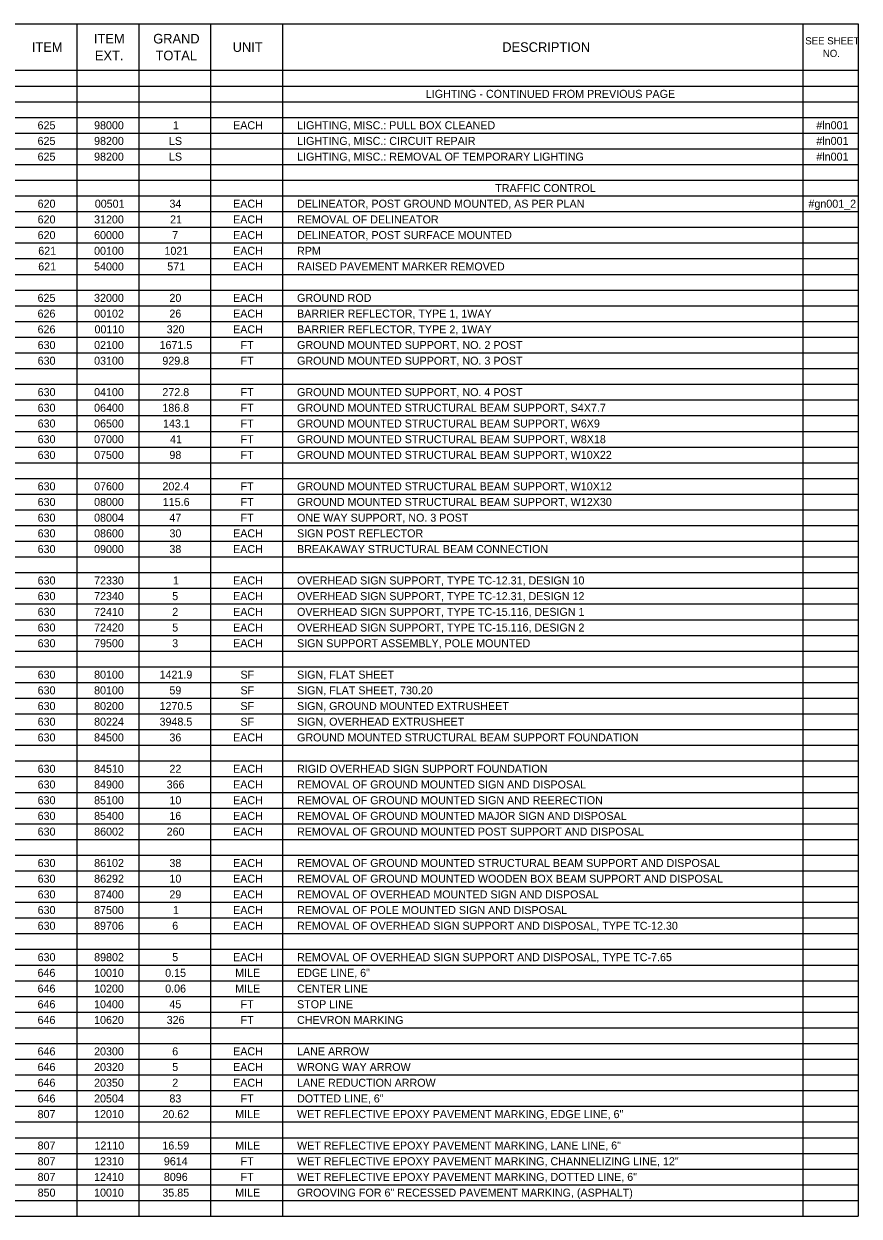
# Model space of a CAD drawing. Extents: x -542 to 295, y -281 to 32.
# Drawn here: x -525.86 to -511.25, y -100.44 to -79.59 of the extents above; entities that cross this region are included whole.
import ezdxf

# ---------------------------------------------------------------- set-up
doc = ezdxf.new("R2010")
doc.units = 0
doc.layers.add('SH_Data', color=7, linetype='Continuous')
doc.layers.add('SH_Text', color=7, linetype='Continuous')

msp = doc.modelspace()

# ---------------------------------------------------------------- linework, layer by layer
at = {"layer": 'SH_Data'}
for p, q in [((-541.766, -79.593), (-511.266, -79.593)), ((-524.93, -79.593), (-524.93, -100.444)), ((-523.845, -79.593), (-523.845, -100.444)), ((-522.589, -79.593), (-522.589, -100.444)), ((-521.333, -79.593), (-521.333, -100.444)), ((-512.235, -79.593), (-512.235, -100.444)), ((-511.266, -79.593), (-511.266, -100.444)), ((-541.766, -80.405), (-511.266, -80.405)), ((-541.766, -80.68), (-511.266, -80.68)), ((-541.766, -80.954), (-511.266, -80.954)), ((-541.766, -81.229), (-511.266, -81.229)), ((-541.766, -81.503), (-511.266, -81.503)), ((-541.766, -81.778), (-511.266, -81.778)), ((-541.766, -82.052), (-511.266, -82.052)), ((-541.766, -82.327), (-511.266, -82.327)), ((-541.766, -82.601), (-511.266, -82.601)), ((-541.766, -82.876), (-511.266, -82.876)), ((-541.766, -83.15), (-511.266, -83.15)), ((-541.766, -83.425), (-511.266, -83.425)), ((-541.766, -83.699), (-511.266, -83.699)), ((-541.766, -83.974), (-511.266, -83.974)), ((-541.766, -84.248), (-511.266, -84.248)), ((-541.766, -84.523), (-511.266, -84.523)), ((-541.766, -84.797), (-511.266, -84.797)), ((-541.766, -85.072), (-511.266, -85.072)), ((-541.766, -85.346), (-511.266, -85.346)), ((-541.766, -85.621), (-511.266, -85.621)), ((-541.766, -85.895), (-511.266, -85.895)), ((-541.766, -86.17), (-511.266, -86.17)), ((-541.766, -86.444), (-511.266, -86.444)), ((-541.766, -86.719), (-511.266, -86.719)), ((-541.766, -86.993), (-511.266, -86.993)), ((-541.766, -87.268), (-511.266, -87.268)), ((-541.766, -87.542), (-511.266, -87.542)), ((-541.766, -87.817), (-511.266, -87.817)), ((-541.766, -88.091), (-511.266, -88.091)), ((-541.766, -88.366), (-511.266, -88.366)), ((-541.766, -88.64), (-511.266, -88.64)), ((-541.766, -88.915), (-511.266, -88.915)), ((-541.766, -89.189), (-511.266, -89.189)), ((-541.766, -89.464), (-511.266, -89.464)), ((-541.766, -89.738), (-511.266, -89.738)), ((-541.766, -90.013), (-511.266, -90.013)), ((-541.766, -90.287), (-511.266, -90.287)), ((-541.766, -90.562), (-511.266, -90.562)), ((-541.766, -90.836), (-511.266, -90.836)), ((-541.766, -91.111), (-511.266, -91.111)), ((-541.766, -91.385), (-511.266, -91.385)), ((-541.766, -91.66), (-511.266, -91.66)), ((-541.766, -91.935), (-511.266, -91.935)), ((-541.766, -92.209), (-511.266, -92.209)), ((-541.766, -92.484), (-511.266, -92.484)), ((-541.766, -92.758), (-511.266, -92.758)), ((-541.766, -93.033), (-511.266, -93.033)), ((-541.766, -93.307), (-511.266, -93.307)), ((-541.766, -93.582), (-511.266, -93.582)), ((-541.766, -93.856), (-511.266, -93.856)), ((-541.766, -94.131), (-511.266, -94.131)), ((-541.766, -94.405), (-511.266, -94.405)), ((-541.766, -94.68), (-511.266, -94.68)), ((-541.766, -94.954), (-511.266, -94.954)), ((-541.766, -95.229), (-511.266, -95.229)), ((-541.766, -95.503), (-511.266, -95.503)), ((-541.766, -95.778), (-511.266, -95.778)), ((-541.766, -96.052), (-511.266, -96.052)), ((-541.766, -96.327), (-511.266, -96.327)), ((-541.766, -96.601), (-511.266, -96.601)), ((-541.766, -96.876), (-511.266, -96.876)), ((-541.766, -97.15), (-511.266, -97.15)), ((-541.766, -97.425), (-511.266, -97.425)), ((-541.766, -97.699), (-511.266, -97.699)), ((-541.766, -97.974), (-511.266, -97.974)), ((-541.766, -98.248), (-511.266, -98.248)), ((-541.766, -98.523), (-511.266, -98.523)), ((-541.766, -98.797), (-511.266, -98.797)), ((-541.766, -99.072), (-511.266, -99.072)), ((-541.766, -99.346), (-511.266, -99.346)), ((-541.766, -99.621), (-511.266, -99.621)), ((-541.766, -99.895), (-511.266, -99.895)), ((-541.766, -100.17), (-511.266, -100.17)), ((-541.766, -100.444), (-511.266, -100.444))]:
    msp.add_line(p, q, dxfattribs=at)

# ---------------------------------------------------------------- texts
at = {"layer": 'SH_Text'}
for s, height, p in [('ITEM', 0.168, (-524.629, -79.936)), ('GRAND ', 0.168, (-523.593, -79.936)), ('SEE SHEET ', 0.126, (-512.192, -79.952)), ('ITEM', 0.168, (-525.715, -80.083)), ('EXT.', 0.168, (-524.613, -80.23)), ('TOTAL', 0.168, (-523.552, -80.23)), ('UNIT', 0.168, (-522.203, -80.083)), ('DESCRIPTION', 0.168, (-517.49, -80.083)), ('NO.', 0.126, (-511.885, -80.172)), ('LIGHTING - CONTINUED FROM PREVIOUS PAGE', 0.14, (-518.826, -80.887)), ('625', 0.14, (-525.615, -81.436)), ('98000', 0.14, (-524.627, -81.436)), ('1', 0.14, (-523.249, -81.436)), ('EACH', 0.14, (-522.196, -81.436)), ('LIGHTING, MISC.: PULL BOX CLEANED', 0.14, (-521.078, -81.436)), ('#ln001', 0.14, (-511.998, -81.436)), ('625', 0.14, (-525.615, -81.71)), ('98200', 0.14, (-524.627, -81.71)), ('LS', 0.14, (-523.318, -81.71)), ('LIGHTING, MISC.: CIRCUIT REPAIR', 0.14, (-521.078, -81.71)), ('#ln001', 0.14, (-511.998, -81.71)), ('625', 0.14, (-525.615, -81.985)), ('98200', 0.14, (-524.627, -81.985)), ('LS', 0.14, (-523.318, -81.985)), ('LIGHTING, MISC.: REMOVAL OF TEMPORARY LIGHTING', 0.14, (-521.078, -81.985)), ('#ln001', 0.14, (-511.998, -81.985)), ('TRAFFIC CONTROL', 0.14, (-517.613, -82.534)), ('620', 0.14, (-525.614, -82.808)), ('00501', 0.14, (-524.615, -82.808)), ('34', 0.14, (-523.309, -82.808)), ('EACH', 0.14, (-522.196, -82.808)), ('DELINEATOR, POST GROUND MOUNTED, AS PER PLAN', 0.14, (-521.078, -82.808)), ('#gn001_2', 0.14, (-512.136, -82.808)), ('620', 0.14, (-525.614, -83.083)), ('31200', 0.14, (-524.627, -83.083)), ('21', 0.14, (-523.298, -83.083)), ('EACH', 0.14, (-522.196, -83.083)), ('REMOVAL OF DELINEATOR', 0.14, (-521.078, -83.083)), ('620', 0.14, (-525.614, -83.357)), ('60000', 0.14, (-524.627, -83.357)), ('7', 0.14, (-523.261, -83.357)), ('EACH', 0.14, (-522.196, -83.357)), ('DELINEATOR, POST SURFACE MOUNTED', 0.14, (-521.078, -83.357)), ('621', 0.14, (-525.603, -83.632)), ('00100', 0.14, (-524.627, -83.632)), ('1021', 0.14, (-523.396, -83.632)), ('EACH', 0.14, (-522.196, -83.632)), ('RPM', 0.14, (-521.078, -83.632)), ('621', 0.14, (-525.603, -83.906)), ('54000', 0.14, (-524.627, -83.906)), ('571', 0.14, (-523.347, -83.906)), ('EACH', 0.14, (-522.196, -83.906)), ('RAISED PAVEMENT MARKER REMOVED', 0.14, (-521.078, -83.906)), ('625', 0.14, (-525.615, -84.455)), ('32000', 0.14, (-524.627, -84.455)), ('20', 0.14, (-523.309, -84.455)), ('EACH', 0.14, (-522.196, -84.455)), ('GROUND ROD', 0.14, (-521.078, -84.455)), ('626', 0.14, (-525.615, -84.73)), ('00102', 0.14, (-524.626, -84.73)), ('26', 0.14, (-523.31, -84.73)), ('EACH', 0.14, (-522.196, -84.73)), ('BARRIER REFLECTOR, TYPE 1, 1WAY', 0.14, (-521.078, -84.73)), ('626', 0.14, (-525.615, -85.005)), ('00110', 0.14, (-524.62, -85.005)), ('320', 0.14, (-523.358, -85.005)), ('EACH', 0.14, (-522.196, -85.005)), ('BARRIER REFLECTOR, TYPE 2, 1WAY', 0.14, (-521.078, -85.005)), ('630', 0.14, (-525.614, -85.279)), ('02100', 0.14, (-524.627, -85.279)), ('1671.5', 0.14, (-523.482, -85.279)), ('FT', 0.14, (-522.065, -85.279)), ('GROUND MOUNTED SUPPORT, NO. 2 POST', 0.14, (-521.078, -85.279)), ('630', 0.14, (-525.614, -85.554)), ('03100', 0.14, (-524.627, -85.554)), ('929.8', 0.14, (-523.433, -85.554)), ('FT', 0.14, (-522.065, -85.554)), ('GROUND MOUNTED SUPPORT, NO. 3 POST', 0.14, (-521.078, -85.554)), ('630', 0.14, (-525.614, -86.103)), ('04100', 0.14, (-524.627, -86.103)), ('272.8', 0.14, (-523.433, -86.103)), ('FT', 0.14, (-522.065, -86.103)), ('GROUND MOUNTED SUPPORT, NO. 4 POST', 0.14, (-521.078, -86.103)), ('630', 0.14, (-525.614, -86.377)), ('06400', 0.14, (-524.627, -86.377)), ('186.8', 0.14, (-523.433, -86.377)), ('FT', 0.14, (-522.065, -86.377)), ('GROUND MOUNTED STRUCTURAL BEAM SUPPORT, S4X7.7', 0.14, (-521.078, -86.377)), ('630', 0.14, (-525.614, -86.652)), ('06500', 0.14, (-524.627, -86.652)), ('143.1', 0.14, (-523.421, -86.652)), ('FT', 0.14, (-522.065, -86.652)), ('GROUND MOUNTED STRUCTURAL BEAM SUPPORT, W6X9', 0.14, (-521.078, -86.652)), ('630', 0.14, (-525.614, -86.926)), ('07000', 0.14, (-524.627, -86.926)), ('41', 0.14, (-523.298, -86.926)), ('FT', 0.14, (-522.065, -86.926)), ('GROUND MOUNTED STRUCTURAL BEAM SUPPORT, W8X18', 0.14, (-521.078, -86.926)), ('630', 0.14, (-525.614, -87.201)), ('07500', 0.14, (-524.627, -87.201)), ('98', 0.14, (-523.31, -87.201)), ('FT', 0.14, (-522.065, -87.201)), ('GROUND MOUNTED STRUCTURAL BEAM SUPPORT, W10X22', 0.14, (-521.078, -87.201)), ('630', 0.14, (-525.614, -87.75)), ('07600', 0.14, (-524.627, -87.75)), ('202.4', 0.14, (-523.432, -87.75)), ('FT', 0.14, (-522.065, -87.75)), ('GROUND MOUNTED STRUCTURAL BEAM SUPPORT, W10X12', 0.14, (-521.078, -87.75)), ('630', 0.14, (-525.614, -88.024)), ('08000', 0.14, (-524.627, -88.024)), ('115.6', 0.14, (-523.426, -88.024)), ('FT', 0.14, (-522.065, -88.024)), ('GROUND MOUNTED STRUCTURAL BEAM SUPPORT, W12X30', 0.14, (-521.078, -88.024)), ('630', 0.14, (-525.614, -88.299)), ('08004', 0.14, (-524.627, -88.299)), ('47', 0.14, (-523.31, -88.299)), ('FT', 0.14, (-522.065, -88.299)), ('ONE WAY SUPPORT, NO. 3 POST', 0.14, (-521.078, -88.299)), ('630', 0.14, (-525.614, -88.573)), ('08600', 0.14, (-524.627, -88.573)), ('30', 0.14, (-523.309, -88.573)), ('EACH', 0.14, (-522.196, -88.573)), ('SIGN POST REFLECTOR', 0.14, (-521.078, -88.573)), ('630', 0.14, (-525.614, -88.848)), ('09000', 0.14, (-524.627, -88.848)), ('38', 0.14, (-523.31, -88.848)), ('EACH', 0.14, (-522.196, -88.848)), ('BREAKAWAY STRUCTURAL BEAM CONNECTION', 0.14, (-521.078, -88.848)), ('630', 0.14, (-525.614, -89.397)), ('72330', 0.14, (-524.627, -89.397)), ('1', 0.14, (-523.249, -89.397)), ('EACH', 0.14, (-522.196, -89.397)), ('OVERHEAD SIGN SUPPORT, TYPE TC-12.31, DESIGN 10', 0.14, (-521.078, -89.397)), ('630', 0.14, (-525.614, -89.671)), ('72340', 0.14, (-524.627, -89.671)), ('5', 0.14, (-523.261, -89.671)), ('EACH', 0.14, (-522.196, -89.671)), ('OVERHEAD SIGN SUPPORT, TYPE TC-12.31, DESIGN 12', 0.14, (-521.078, -89.671)), ('630', 0.14, (-525.614, -89.946)), ('72410', 0.14, (-524.627, -89.946)), ('2', 0.14, (-523.26, -89.946)), ('EACH', 0.14, (-522.196, -89.946)), ('OVERHEAD SIGN SUPPORT, TYPE TC-15.116, DESIGN 1', 0.14, (-521.078, -89.946)), ('630', 0.14, (-525.614, -90.22)), ('72420', 0.14, (-524.627, -90.22)), ('EACH', 0.14, (-522.196, -90.22)), ('OVERHEAD SIGN SUPPORT, TYPE TC-15.116, DESIGN 2', 0.14, (-521.078, -90.22)), ('5', 0.14, (-523.261, -90.22)), ('630', 0.14, (-525.614, -90.495)), ('79500', 0.14, (-524.627, -90.495)), ('3', 0.14, (-523.261, -90.495)), ('EACH', 0.14, (-522.196, -90.495)), ('SIGN SUPPORT ASSEMBLY, POLE MOUNTED', 0.14, (-521.078, -90.495)), ('630', 0.14, (-525.614, -91.044)), ('80100', 0.14, (-524.627, -91.044)), ('1421.9', 0.14, (-523.482, -91.044)), ('SF', 0.14, (-522.068, -91.044)), ('SIGN, FLAT SHEET', 0.14, (-521.078, -91.044)), ('630', 0.14, (-525.614, -91.318)), ('80100', 0.14, (-524.627, -91.318)), ('59', 0.14, (-523.31, -91.318)), ('SF', 0.14, (-522.068, -91.318)), ('SIGN, FLAT SHEET, 730.20', 0.14, (-521.078, -91.318)), ('630', 0.14, (-525.614, -91.593)), ('80200', 0.14, (-524.627, -91.593)), ('1270.5', 0.14, (-523.482, -91.593)), ('SF', 0.14, (-522.068, -91.593)), ('SIGN, GROUND MOUNTED EXTRUSHEET', 0.14, (-521.078, -91.593)), ('630', 0.14, (-525.614, -91.867)), ('80224', 0.14, (-524.627, -91.867)), ('3948.5', 0.14, (-523.482, -91.867)), ('SF', 0.14, (-522.068, -91.867)), ('SIGN, OVERHEAD EXTRUSHEET', 0.14, (-521.078, -91.867)), ('630', 0.14, (-525.614, -92.142)), ('84500', 0.14, (-524.627, -92.142)), ('36', 0.14, (-523.31, -92.142)), ('EACH', 0.14, (-522.196, -92.142)), ('GROUND MOUNTED STRUCTURAL BEAM SUPPORT FOUNDATION', 0.14, (-521.078, -92.142)), ('630', 0.14, (-525.614, -92.691)), ('84510', 0.14, (-524.627, -92.691)), ('22', 0.14, (-523.309, -92.691)), ('EACH', 0.14, (-522.196, -92.691)), ('RIGID OVERHEAD SIGN SUPPORT FOUNDATION', 0.14, (-521.078, -92.691)), ('630', 0.14, (-525.614, -92.965)), ('84900', 0.14, (-524.627, -92.965)), ('366', 0.14, (-523.358, -92.965)), ('EACH', 0.14, (-522.196, -92.965)), ('REMOVAL OF GROUND MOUNTED SIGN AND DISPOSAL', 0.14, (-521.078, -92.965)), ('630', 0.14, (-525.614, -93.24)), ('85100', 0.14, (-524.627, -93.24)), ('10', 0.14, (-523.309, -93.24)), ('EACH', 0.14, (-522.196, -93.24)), ('REMOVAL OF GROUND MOUNTED SIGN AND REERECTION', 0.14, (-521.078, -93.24)), ('630', 0.14, (-525.614, -93.514)), ('85400', 0.14, (-524.627, -93.514)), ('16', 0.14, (-523.31, -93.514)), ('EACH', 0.14, (-522.196, -93.514)), ('REMOVAL OF GROUND MOUNTED MAJOR SIGN AND DISPOSAL', 0.14, (-521.078, -93.514)), ('630', 0.14, (-525.614, -93.789)), ('86002', 0.14, (-524.626, -93.789)), ('260', 0.14, (-523.358, -93.789)), ('EACH', 0.14, (-522.196, -93.789)), ('REMOVAL OF GROUND MOUNTED POST SUPPORT AND DISPOSAL', 0.14, (-521.078, -93.789)), ('630', 0.14, (-525.614, -94.338)), ('86102', 0.14, (-524.626, -94.338)), ('38', 0.14, (-523.31, -94.338)), ('EACH', 0.14, (-522.196, -94.338)), ('REMOVAL OF GROUND MOUNTED STRUCTURAL BEAM SUPPORT AND DISPOSAL', 0.14, (-521.078, -94.338)), ('630', 0.14, (-525.614, -94.612)), ('86292', 0.14, (-524.626, -94.612)), ('10', 0.14, (-523.309, -94.612)), ('EACH', 0.14, (-522.196, -94.612)), ('REMOVAL OF GROUND MOUNTED WOODEN BOX BEAM SUPPORT AND DISPOSAL', 0.14, (-521.078, -94.612)), ('630', 0.14, (-525.614, -94.887)), ('87400', 0.14, (-524.627, -94.887)), ('29', 0.14, (-523.31, -94.887)), ('EACH', 0.14, (-522.196, -94.887)), ('REMOVAL OF OVERHEAD MOUNTED SIGN AND DISPOSAL', 0.14, (-521.078, -94.887)), ('630', 0.14, (-525.614, -95.161)), ('87500', 0.14, (-524.627, -95.161)), ('1', 0.14, (-523.249, -95.161)), ('EACH', 0.14, (-522.196, -95.161)), ('REMOVAL OF POLE MOUNTED SIGN AND DISPOSAL', 0.14, (-521.078, -95.161)), ('630', 0.14, (-525.614, -95.436)), ('89706', 0.14, (-524.627, -95.436)), ('6', 0.14, (-523.261, -95.436)), ('EACH', 0.14, (-522.196, -95.436)), ('REMOVAL OF OVERHEAD SIGN SUPPORT AND DISPOSAL, TYPE TC-12.30', 0.14, (-521.078, -95.436)), ('630', 0.14, (-525.614, -95.985)), ('89802', 0.14, (-524.626, -95.985)), ('5', 0.14, (-523.261, -95.985)), ('EACH', 0.14, (-522.196, -95.985)), ('REMOVAL OF OVERHEAD SIGN SUPPORT AND DISPOSAL, TYPE TC-7.65', 0.14, (-521.078, -95.985)), ('646', 0.14, (-525.615, -96.259)), ('10010', 0.14, (-524.627, -96.259)), ('0.15', 0.14, (-523.384, -96.259)), ('MILE', 0.14, (-522.16, -96.259)), ('EDGE LINE, 6"', 0.14, (-521.078, -96.259)), ('646', 0.14, (-525.615, -96.534)), ('10200', 0.14, (-524.627, -96.534)), ('0.06', 0.14, (-523.384, -96.534)), ('MILE', 0.14, (-522.16, -96.534)), ('CENTER LINE', 0.14, (-521.078, -96.534)), ('646', 0.14, (-525.615, -96.808)), ('10400', 0.14, (-524.627, -96.808)), ('45', 0.14, (-523.31, -96.808)), ('FT', 0.14, (-522.065, -96.808)), ('STOP LINE', 0.14, (-521.078, -96.808)), ('646', 0.14, (-525.615, -97.083)), ('10620', 0.14, (-524.627, -97.083)), ('326', 0.14, (-523.358, -97.083)), ('FT', 0.14, (-522.065, -97.083)), ('CHEVRON MARKING', 0.14, (-521.078, -97.083)), ('646', 0.14, (-525.615, -97.632)), ('20300', 0.14, (-524.627, -97.632)), ('6', 0.14, (-523.261, -97.632)), ('EACH', 0.14, (-522.196, -97.632)), ('LANE ARROW', 0.14, (-521.078, -97.632)), ('646', 0.14, (-525.615, -97.906)), ('20320', 0.14, (-524.627, -97.906)), ('5', 0.14, (-523.261, -97.906)), ('EACH', 0.14, (-522.196, -97.906)), ('WRONG WAY ARROW', 0.14, (-521.078, -97.906)), ('646', 0.14, (-525.615, -98.181)), ('20350', 0.14, (-524.627, -98.181)), ('2', 0.14, (-523.26, -98.181)), ('EACH', 0.14, (-522.196, -98.181)), ('LANE REDUCTION ARROW', 0.14, (-521.078, -98.181)), ('646', 0.14, (-525.615, -98.456)), ('20504', 0.14, (-524.627, -98.456)), ('83', 0.14, (-523.31, -98.456)), ('FT', 0.14, (-522.065, -98.456)), ('DOTTED LINE, 6"', 0.14, (-521.078, -98.456)), ('807', 0.14, (-525.615, -98.73)), ('12010', 0.14, (-524.627, -98.73)), ('20.62', 0.14, (-523.432, -98.73)), ('MILE', 0.14, (-522.16, -98.73)), ('WET REFLECTIVE EPOXY PAVEMENT MARKING, EDGE LINE, 6"', 0.14, (-521.078, -98.73)), ('807', 0.14, (-525.615, -99.279)), ('12110', 0.14, (-524.62, -99.279)), ('16.59', 0.14, (-523.433, -99.279)), ('MILE', 0.14, (-522.16, -99.279)), ('WET REFLECTIVE EPOXY PAVEMENT MARKING, LANE LINE, 6"', 0.14, (-521.078, -99.279)), ('807', 0.14, (-525.615, -99.554)), ('12310', 0.14, (-524.627, -99.554)), ('9614', 0.14, (-523.407, -99.554)), ('FT', 0.14, (-522.065, -99.554)), ('WET REFLECTIVE EPOXY PAVEMENT MARKING, CHANNELIZING LINE, 12"', 0.14, (-521.078, -99.554)), ('807', 0.14, (-525.615, -99.828)), ('12410', 0.14, (-524.627, -99.828)), ('8096', 0.14, (-523.407, -99.828)), ('FT', 0.14, (-522.065, -99.828)), ('WET REFLECTIVE EPOXY PAVEMENT MARKING, DOTTED LINE, 6"', 0.14, (-521.078, -99.828)), ('850', 0.14, (-525.614, -100.103)), ('10010', 0.14, (-524.627, -100.103)), ('35.85', 0.14, (-523.433, -100.103)), ('MILE', 0.14, (-522.16, -100.103)), ('GROOVING FOR 6" RECESSED PAVEMENT MARKING, (ASPHALT)', 0.14, (-521.078, -100.103))]:
    msp.add_text(s, height=height, dxfattribs=at).set_placement(p)

doc.saveas('drawing.dxf')
